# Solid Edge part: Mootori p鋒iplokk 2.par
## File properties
Author: KULL
Template: Iso Metric Part.par
Last saved by: KULL
Revision: 77
Application: Solid Edge
Density: 6920,000 kg/m^3
Accuracy: 0,990
Material: Iron, grey cast type 60
Face Style: Gray
Fill Style: ANSI31(Iron)
Virtual Style: ANSI31(Iron)
Categorization: Metals\Iron
LibraryName: Materials
Coef. of Thermal Exp: 1.1e-05
Thermal Conductivity: 48.0
Specific Heat: 544.0
Modulus of Elasticity: 158579411000.0
Poisson's Ratio: 0.29
Yield Stress: 275790291.72673446
Ultimate Stress: 413685437.59010166
Elongation: 0.0
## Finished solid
Body 1: sheet body, 1 face, 52 edges, 52 vertices.
  Faces by surface: plane 1
  Edges by curve: line 32, circle 20
Body 2: sheet body, 3 faces, 38 edges, 38 vertices.
  Faces by surface: plane 3
  Edges by curve: line 24, circle 14
Body 3: solid body, 322 faces, 758 edges, 428 vertices.
  Faces by surface: cylinder 146, plane 70, blend 60, torus 46
  Edges by curve: line 314, circle 292, ellipse 76, intersection 76
Body 4: sheet body, 1 face, 12 edges, 12 vertices.
  Faces by surface: plane 1
  Edges by curve: line 7, circle 5
Body 5: sheet body, 1 face, 12 edges, 12 vertices.
  Faces by surface: plane 1
  Edges by curve: line 7, circle 5
Body 6: sheet body, 1 face, 12 edges, 12 vertices.
  Faces by surface: plane 1
  Edges by curve: line 7, circle 5
Body 7: sheet body, 1 face, 12 edges, 12 vertices.
  Faces by surface: plane 1
  Edges by curve: line 7, circle 5
Bounding box of the edges (mm; curved faces can reach further): 102.794 x 75.076 x 42.971, from (-51.3987, -39.4607, 38.005) to (51.3957, 35.6155, 80.9761).
Cylindrical faces by radius (mm): R0.1 x22, R1.4 x56, R3 x28, R4 x4, R6 x14, R8 x18, R9.5 x2, R10 x2
Toroidal faces (ring radius, tube radius in mm): R1.6 r1.4 x20, R7 r1 x10, R7.8 r0.2 x2, R7.9 r0.1 x4, R8.2 r0.2 x2, R9.3 r0.2 x2, R11.5 r2 x2, R18 r8 x4
Planar faces by outward normal: +x 8, +z 1, -x 8, -z 17, oblique 36
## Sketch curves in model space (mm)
line (48, 16.5423, 30.5002) -> (48, -16.5423, 30.5002)
line (48, -16.5423, 30.5002) -> (48, 16.5423, 30.5002)
circle centre (48, 0, 38.6638) radius 9.5
circle centre (48, 0, 38.6638) radius 8
circle centre (48, 0, 38.6638) radius 15.3056
line (48, -15.1609, 77.7496) -> (48, -12.5898, 74.6854)
line (48, -12.5898, 74.6854) -> (48, 12.5898, 74.6854)
line (48, 15.1609, 77.7496) -> (48, 12.5898, 74.6854)
line (48, 15.1609, 77.7496) -> (48, 35.6155, 60.5862)
line (48, 35.6155, 60.5862) -> (48, 20.5423, 42.6226)
line (48, 20.5423, 42.6226) -> (48, 20.5423, 26.5002)
line (48, 20.5423, 26.5002) -> (48, -20.5423, 26.5002)
line (48, -20.5423, 26.5002) -> (48, -20.5423, 42.6226)
line (48, -20.5423, 42.6226) -> (48, -35.6155, 60.5862)
line (48, -35.6155, 60.5862) -> (48, -15.1609, 77.7496)
line (48, 16.5423, 44.0785) -> (48, 16.5423, 30.5002)
line (48, 29.9802, 60.0931) -> (48, 16.5423, 44.0785)
line (48, 15.654, 72.1143) -> (48, 29.9802, 60.0931)
line (48, 14.455, 70.6854) -> (48, 15.654, 72.1143)
line (48, -14.455, 70.6854) -> (48, 14.455, 70.6854)
line (48, -15.654, 72.1143) -> (48, -14.455, 70.6854)
line (48, -16.5423, 30.5002) -> (48, -16.5423, 44.0785)
line (48, -16.5423, 44.0785) -> (48, -29.9802, 60.0931)
line (48, -29.9802, 60.0931) -> (48, -15.654, 72.1143)
line (48, 15.9009, 66.6854) -> (48, 24.3449, 59.6001)
line (48, 24.3449, 59.6001) -> (48, 12.5423, 45.5344)
line (48, 12.5423, 45.5344) -> (48, 12.5423, 34.5002)
line (48, 12.5423, 34.5002) -> (48, -12.5423, 34.5002)
line (48, -12.5423, 34.5002) -> (48, -12.5423, 45.5344)
line (48, -12.5423, 45.5344) -> (48, -24.3449, 59.6001)
line (48, -24.3449, 59.6001) -> (48, -15.9009, 66.6854)
line (48, -15.9009, 66.6854) -> (48, 15.9009, 66.6854)
line (48, 33.0444, 57.522) -> (-48, 33.0444, 57.522)
line (-48, 33.0444, 57.522) -> (-48, 12.5898, 74.6854)
line (-48, 12.5898, 74.6854) -> (48, 12.5898, 74.6854)
line (48, 12.5898, 74.6854) -> (48, 33.0444, 57.522)
line (48, -12.5898, 74.6854) -> (48, -33.0444, 57.522)
line (48, -33.0444, 57.522) -> (-48, -33.0444, 57.522)
line (-48, -33.0444, 57.522) -> (-48, -12.5898, 74.6854)
line (-48, -12.5898, 74.6854) -> (48, -12.5898, 74.6854)
line (0, -20.5423, 42.6226) -> (0, -20.5423, 37.4805)
line (0, -21.5469, 43.8199) -> (0, -20.5423, 42.6226)
line (0, -20.5423, 37.4805) -> (0, -18.158, 22.4349)
line (0, 20.5423, 42.6226) -> (0, 20.5423, 37.4805)
line (0, 21.5469, 43.8199) -> (0, 20.5423, 42.6226)
line (0, 20.5423, 37.4805) -> (0, 18.158, 22.4349)
line (0, -20.5423, 42.6226) -> (0, -20.5423, 37.4805)
line (0, -21.5469, 43.8199) -> (0, -20.5423, 42.6226)
line (0, -20.5423, 37.4805) -> (0, -18.158, 22.4349)
line (0, 20.5423, 42.6226) -> (0, 20.5423, 37.4805)
line (0, 21.5469, 43.8199) -> (0, 20.5423, 42.6226)
line (0, 20.5423, 37.4805) -> (0, 18.158, 22.4349)
line (0, -17.9423, 25.0349) -> (0, -12.1902, 25.0349)
line (0, -17.9423, 46.8445) -> (0, -17.9423, 25.0349)
line (0, -15.9159, 48.5449) -> (0, -17.9423, 46.8445)
line (0, -15.9159, 48.5449) -> (0, -12.1902, 25.0349)
line (0, 17.9423, 25.0349) -> (0, 12.1902, 25.0349)
line (0, 17.9423, 46.8445) -> (0, 17.9423, 25.0349)
line (0, 15.9159, 48.5449) -> (0, 17.9423, 46.8445)
line (0, -17.9423, 25.0349) -> (0, -12.1902, 25.0349)
line (0, -17.9423, 46.8445) -> (0, -17.9423, 25.0349)
line (0, -15.9159, 48.5449) -> (0, -17.9423, 46.8445)
line (0, 17.9423, 25.0349) -> (0, 12.1902, 25.0349)
line (0, 17.9423, 46.8445) -> (0, 17.9423, 25.0349)
line (0, 15.9159, 48.5449) -> (0, 17.9423, 46.8445)
line (0, 15.9159, 48.5449) -> (0, 12.1902, 25.0349)
line (0, -1.6194, 61.6114) -> (0, 1.6194, 61.6114)
line (0, -12.5898, 74.6854) -> (0, -1.6194, 61.6114)
line (0, -12.5898, 74.6854) -> (0, 12.5898, 74.6854)
circle centre (0, 0, 38.6638) radius 4
line (0, -41.2162, 67.2608) -> (0, -20.5423, 42.6226)
line (0, -41.2162, 67.2608) -> (0, -20.7617, 84.4243)
line (0, -20.7617, 84.4243) -> (0, -12.5898, 74.6854)
line (0, -21.5469, 43.8199) -> (0, -23.6514, 42.054)
line (0, -18.158, 22.4349) -> (0, -20.5423, 22.4349)
line (0, -20.5423, 22.4349) -> (0, -23.6514, 42.054)
line (0, 21.5469, 43.8199) -> (0, 23.6514, 42.054)
line (0, 18.158, 22.4349) -> (0, 20.5423, 22.4349)
line (0, 20.5423, 22.4349) -> (0, 23.6514, 42.054)
line (0, 10.4081, 72.0854) -> (0, 12.5898, 74.6854)
line (0, 1.6194, 61.6114) -> (0, 10.4081, 72.0854)
line (0, -10.9191, 72.6944) -> (0, -1.6194, 61.6114)
line (0, -1.6194, 61.6114) -> (0, -2.7629, 61.6114)
line (0, -2.7629, 61.6114) -> (0, -11.5902, 72.1314)
line (0, -11.5902, 72.1314) -> (0, -10.9191, 72.6944)
line (0, 2.7629, 61.6114) -> (0, 1.6194, 61.6114)
line (0, 11.5902, 72.1314) -> (0, 2.7629, 61.6114)
line (0, 1.6194, 61.6114) -> (0, 10.9191, 72.6944)
line (0, 10.9191, 72.6944) -> (0, 11.5902, 72.1314)
line (0, 3.8574, 53.4416) -> (0, -1.9287, 55.0599)
line (0, -1.9287, 55.0599) -> (0, -3.8574, 53.4416)
line (0, -3.8574, 53.4416) -> (0, 3.8574, 53.4416)
line (0, 2.0773, 61.6114) -> (0, -2.0773, 61.6114)
line (0, -2.0773, 61.6114) -> (0, 0, 59.1358)
line (0, 0, 59.1358) -> (0, 2.0773, 61.6114)
line (0, 0, 82.3136) -> (0, 39.108, 82.3136)
line (0, 39.108, 82.3136) -> (0, 39.108, 23.2994)
line (0, 39.108, 23.2994) -> (0, 0, 23.2994)
line (0, 0, 23.2994) -> (0, 0, 82.3136)
line (0, 0, 81.7842) -> (0, -39.844, 81.7842)
line (0, -39.844, 81.7842) -> (0, -39.844, 0)
line (0, -39.844, 0) -> (0, 0, 0)
line (0, 0, 0) -> (0, 0, 81.7842)
line (0, 41.2162, 67.2608) -> (0, 20.5423, 42.6226)
line (0, 41.2162, 67.2608) -> (0, 20.7617, 84.4243)
line (0, 20.7617, 84.4243) -> (0, 12.5898, 74.6854)
line (0, 20.5423, 42.6226) -> (0, 20.5423, 26.5002)
line (0, 20.5423, 26.5002) -> (0, 0, 26.5002)
line (0, -20.5423, 26.5002) -> (0, 0, 26.5002)
line (0, -20.5423, 42.6226) -> (0, -20.5423, 26.5002)
line (0, 12.5898, 74.6854) -> (0, 0, 74.6854)
line (0, -12.5898, 74.6854) -> (0, 0, 74.6854)
arc centre (-18, -25.3882, 69.1679) radius 9 from (-10.8482, -29.5736, 65.6559) through (-18.2666, -32.2796, 63.3853) to (-25.1518, -29.5736, 65.6559)
line (-10.8482, -29.5736, 65.6559) -> (-7.1518, -29.5736, 65.6559)
arc centre (0, -25.3882, 69.1679) radius 9 from (7.1518, -29.5736, 65.6559) through (-0.2666, -32.2796, 63.3853) to (-7.1518, -29.5736, 65.6559)
line (7.1518, -29.5736, 65.6559) -> (10.8482, -29.5736, 65.6559)
arc centre (18, -25.3882, 69.1679) radius 9 from (25.1518, -29.5736, 65.6559) through (17.7334, -32.2796, 63.3853) to (10.8482, -29.5736, 65.6559)
line (25.1518, -29.5736, 65.6559) -> (28.8482, -29.5736, 65.6559)
arc centre (36, -25.3882, 69.1679) radius 9 from (42.3572, -30.2685, 65.0728) through (35.1337, -32.2506, 63.4097) to (28.8482, -29.5736, 65.6559)
line (42.3572, -39.4607, 57.3596) -> (42.3572, -30.2685, 65.0728)
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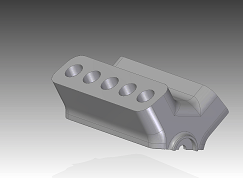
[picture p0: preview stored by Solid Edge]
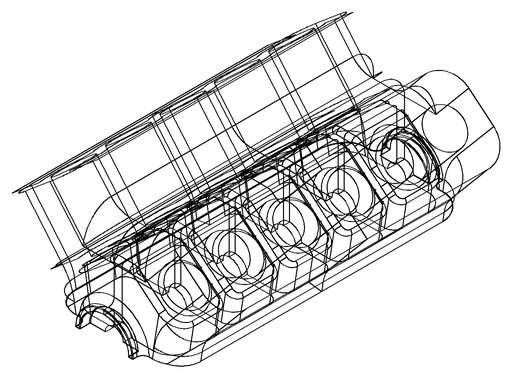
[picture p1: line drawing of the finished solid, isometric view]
